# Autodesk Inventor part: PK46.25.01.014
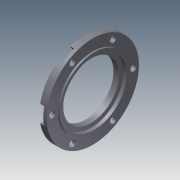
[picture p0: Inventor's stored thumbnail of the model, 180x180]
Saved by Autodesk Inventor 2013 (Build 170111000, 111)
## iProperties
Created: 2005-04
Part Number: PK46.25.01.014
Material: Steel, Mild
Document SubType Name: Modeling
Designer: salex
Manufacturer: Standard
Standards Organization: Custom
Density: 7.86 g/cm^3
Author: salex
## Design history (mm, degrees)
sketch "Эскиз1"
  geometry: L1 (0, 0)-(97.878, 0); L2 (0, 82.5)-(0, 50); L3 (0, 50)-(10, 50); L4 (10, 50)-(10, 57.5); L5 (10, 57.5)-(16, 57.5); L6 (16, 57.5)-(16, 62.5); L7 (16, 62.5)-(13, 62.5); L8 (13, 62.5)-(13, 82.5); L9 (13, 82.5)-(0, 82.5)
  constraints: 18 end point, 6 parallel, 2 perpendicular, 1 horizontal, 1 other
  dimensions: "d0" = 0 distance from line of L1.start L2; "d1" = 165 diameter of L9 L1; "d2" = 100 diameter of L3 L1; "d3" = 115 diameter of L5 L1; "d4" = 125 diameter of L7 L1; "d5" = 3 distance of L6.end L7.end; "d6" = 16 distance between parallel lines of L6 L2; "d7" = 6 distance between parallel lines of L6 L4
revolve "Вращение1" sketch "Эскиз1" stored, may be unused: angle "d8" = 90 deg
sketch "Эскиз2"
  geometry: C1 r 82.5 at (0, 0) reference; C2 r 5.5 at (0, 72.5)
  constraints: 1 centre point
  dimensions: "d9" = 11 diameter of C2; "d10" = 0 horizontal distance of C1.centre C2.centre; "d11" = 72.5 distance of C1.centre C2.centre
extrude "Выдавливание1" cut sketch "Эскиз2" stored distance "d12" = 10; taper "d13" = 0 deg
sketch "Эскиз3"
  geometry: L1 (0, 0)-(0, 72.5); L2 (15, 72.5)-(15, 81.125); L3 (-15, 72.5)-(-15, 81.125); C1 r 5.5 at (0, 72.5) reference; C2 r 50 at (0, 0) reference; A1 r 15 centre (0, 72.5) between (-15, 72.5) and (15, 72.5); A2 r 82.5 centre (0, 0) between (-15, 81.125) and (15, 81.125) reference
  constraints: 6 end point, 4 point on circle, 2 parallel, 2 tangent, 1 centre point, 1 coincident, 1 vertical
  dimensions: "d17" = 30 diameter of A1
extrude "Выдавливание2" cut sketch "Эскиз3" distance "d18" = 7; taper "d19" = 0 deg
pattern_circular "Круговой массив1" dims angle "d16" = 360 deg
body "Solid1"
